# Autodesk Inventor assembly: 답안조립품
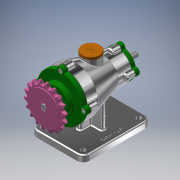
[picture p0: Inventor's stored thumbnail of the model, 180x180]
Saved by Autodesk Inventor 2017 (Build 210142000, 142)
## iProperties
Part Number: 답안조립품
Material: 일반
Document SubType Name: Assembly
Designer: 222
Author: 222
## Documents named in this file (15)
- C:\Users\222\Desktop\701206V1011\답안조립품.iam
- C:\Users\222\Desktop\701206V1011\본체.ipt
- C:\Users\222\Desktop\701206V1011\개스킷 A.ipt
- C:\Users\222\Desktop\701206V1011\개스킷 B.ipt
- C:\Users\222\Desktop\701206V1011\뒤커버.ipt
- C:\Users\222\Desktop\701206V1011\마개.ipt
- C:\Users\222\Desktop\701206V1011\베어링 6200.ipt
- C:\Users\222\Desktop\701206V1011\베어링 6203.ipt
- C:\Users\222\Desktop\701206V1011\볼트 M5.ipt
- C:\Users\222\Desktop\701206V1011\스프로킷.ipt
- C:\Users\222\Desktop\701206V1011\앞커버.ipt
- C:\Users\222\Desktop\701206V1011\오일 실 10 20 7.ipt
- C:\Users\222\Desktop\701206V1011\오일 실 17 30 8.ipt
- C:\Users\222\Desktop\701206V1011\축.ipt
- C:\Users\222\Desktop\701206V1011\키 4x4x14.ipt
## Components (2 placed, 2 different names)
1. 개스킷 A:1
2. 개스킷 B:1
